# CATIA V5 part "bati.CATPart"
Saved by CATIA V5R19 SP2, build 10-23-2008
Part number: bati
Material "Acier": density 7860 kg/m3, Young's modulus 2e+11 Pa, Poisson ratio 0.266, thermal expansion 1.17e-05 1/K
Material "Bleu clair DS": density 7860 kg/m3, Young's modulus 2e+11 Pa, Poisson ratio 0.266
Bounding box of the stored display mesh (mm): x -60 to 60, y -200 to 200, z 0 to 190
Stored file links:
  C:\Documents and Settings\jboiteux\Bureau\iao_jboiteux\Catia\non optiisé\iao final\bati.CATPart
  C:\iao\acanisme a coulisseau.CATProduct
  C:\iao\squelette bati.CATPart
  C:\Appli\Dassault Systemes\B20\intel_a\startup\materials\French\Catalog.CATMaterial
  C:\Appli\Dassault Systemes\B20\intel_a\startup\materials\bright_oak.jpg
  C:\Appli\Dassault Systemes\B20\intel_a\startup\materials\blue_env_512x512.jpg
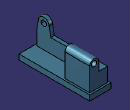
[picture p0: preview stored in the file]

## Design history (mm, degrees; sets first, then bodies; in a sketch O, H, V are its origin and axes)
Parameters
  taille = 10 mm
Set1
  Plane1 to Plane3: linked copy from another document
Body1 (main body), material "Acier"
  Sketch1 on xy-plane, origin (0, 0, 0), H (1, 0, 0), V (0, 1, 0)
    line L1 (-60, 200) -> (60, 200)
    line L2 (60, 200) -> (60, -200)
    line L3 (60, -200) -> (-60, -200)
    line L4 (-60, -200) -> (-60, 200)
    distance H L3 = 200 {= taille *20}
    distance L1 H = 200 {= taille *20}
    distance V L2 = 60 {= taille *6}
    distance L4 V = 60 {= taille *6}
    horizontal: L1 H, L3 H
    vertical: L2 V, L4 V
  Pad1: profile Sketch1, direction (0, 0, 1), length 30 {= taille *3}
  Sketch2 on end face of Pad1, origin (0, 0, 30), H (1, 0, 0), V (0, 1, 0)
    point P1 (0, 190)
    line L1 (0, 190) -> (50, 190)
    line L2 (50, 190) -> (50, 50)
    line L3 (50, 50) -> (0, 50)
    line L4 (0, 50) -> (0, 190)
    reference projected line E1 (60, -20) -> (60, 20) from edge [face of Pad1 from Sketch1.L2 | end face of Pad1]
    reference projected line E2 (6, 200) -> (-6, 200) from edge [face of Pad1 from Sketch1.L1 | end face of Pad1]
    distance L2 E1 = 10 {= taille}
    distance E2 L1 = 10 {= taille}
    length L2 = 140 {= taille*14}
    angle L4 L3 = 90
    coincidence: P1 V
    horizontal: L1 H
    vertical: L4 V
  Pad2: profile Sketch2, direction (0, 0, 1), length 130 {= taille *13}
  Sketch3 on face of Pad2 from Sketch2.L3, origin (0, 50, 0), H (1, 0, 0), V (0, 0, 1)
    arc A1 centre (25, 160) radius 25 from (50, 160) to (0, 160) ccw
    point P1 (25, 160)
    point P2 (0, 160)
    point P3 (50, 160)
    line L1 (0, 160) -> (50, 160)
    reference projected line E1 (0, 160) -> (6, 160) from edge [face of Pad2 from Sketch2.L3 | end face of Pad2]
    reference projected line E2 (0, 3) -> (0, 16) from edge [face of Pad2 from Sketch2.L3 | face of Pad2 from Sketch2.L4]
    reference projected line E3 (50, 3) -> (50, 16) from edge [face of Pad2 | face of Pad2 from Sketch2.L3]
    coincidence: P2 V, L1 P1, E1 L1, E2 P2, E3 P3
  Pad3: profile Sketch3, direction (0, 1, 0), length 140 {= taille *14}
  Sketch4 on face of Pad1 from Sketch1.L3, origin (0, -200, 0), H (1, 0, 0), V (0, 0, 1)
    line L1 (-50, 30) -> (-30, 30)
    line L2 (-30, 30) -> (-30, 110)
    line L3 (-30, 110) -> (-50, 110)
    line L4 (-50, 110) -> (-50, 30)
    reference projected line E1 (-6, 30) -> (6, 30) from edge [face of Pad1 from Sketch1.L3 | end face of Pad1]
    reference projected line E2 (-60, 0) -> (-60, 3) from edge [face of Pad1 from Sketch1.L3 | face of Pad1 from Sketch1.L4]
    length L2 = 80 {= taille *8}
    length L3 = 20 {= taille *2}
    distance E2 L4 = 10 {= taille}
    horizontal: L1 H, L3 H
    vertical: L2 V, L4 V
    coincidence: E1 L1
  Pad4: profile Sketch4, direction (0, 1, 0), length 390 {= taille*39}, opposite side length -10 {= -taille}
  Sketch5 on face of Pad2 from Sketch2.L4, origin (0, 0, 0), H (0, -1, 0), V (0, 0, 1)
    line L1 (-190, 110) -> (-50, 110)
    line L2 (-50, 110) -> (-50, 30)
    line L3 (-50, 30) -> (-190, 30)
    line L4 (-190, 30) -> (-190, 110)
    reference projected line E1 (19, 110) -> (-19, 110) from edge [face of Pad4 from Sketch4.L3 | face of Pad4 from Sketch4.L4]
    reference projected line E2 (-20, 30) -> (20, 30) from edge [face of Pad1 from Sketch1.L4 | end face of Pad1]
    reference projected line E3 (-190, 11) -> (-190, 3) from edge [face of Pad4 | face of Pad4]
    reference projected line E4 (-50, 3) -> (-50, 16) from edge [face of Pad2 from Sketch2.L2 | face of Pad3]
    horizontal: L1 H, L3 H
    vertical: L2 V, L4 V
    coincidence: E1 L1, E2 L3, E3 L4, E4 L2
  Pad5: profile Sketch5, direction (-1, 0, 0), up to the existing solid (limit type 2)
  Sketch6 on face of Pad4 from Sketch4.L2, origin (-30, 0, 0), H (0, 1, 0), V (0, 0, 1)
    arc A1 centre (-150, 160) radius 30 from (-120, 160) to (-180, 160) ccw
    point P1 (-150, 160)
    point P2 (-120, 160)
    point P3 (-180, 160)
    line L1 (-120, 160) -> (-110, 110)
    point P4 (-110, 110)
    point P5 (-110, 110)
    line L2 (-110, 110) -> (-190, 110)
    point P6 (-190, 110)
    line L3 (-190, 110) -> (-180, 160)
    reference projected line E1 (-19, 110) -> (19, 110) from edge [face of Pad4 from Sketch4.L2 | face of Pad4]
    reference projected point E2 (-190, 110) from vertex [start face of Pad4 | face of Pad4 from Sketch4.L3 | face of Pad4 from Sketch4.L2]
    reference projected line E3 (-200, 0) -> (-200, 3) from edge [face of Pad1 from Sketch1.L2 | face of Pad1 from Sketch1.L3]
    distance P6 P5 = 80 {= taille *8}
    distance P2 P3 = 60 {= taille *6}
    distance P3 P1 = 30 {= taille*3}
    distance P1 L2 = 50 {= taille *5}
    distance P2 L2 = 50 {= taille *5}
    distance P1 E3 = 50 {= taille*5}
    horizontal: L2 H
    coincidence: P5 P4, E1 L2, E2 P6
  Pad6: profile Sketch6, direction (-1, 0, 0), up to face of Pad4 from Sketch4.L4
  Sketch7 on face of Pad4, origin (-50, -15.2449, 16.9389), H (0, 1, 0), V (0, 0, -1)
    point P1 (-134.7551, -143.0611)
    reference projected arc E1 centre (-134.7551, -143.0611) radius 30 from (-164.7551, -143.0611) to (-104.7551, -143.0611) ccw from edge [end face of Pad6 | face of Pad6 from Sketch6.A1]
    concentricity: E1 P1
  Hole1: placed by Sketch7, at (-50, -150, 160) direction (1, 0, 0), diameter 30 {= taille*3}, through (limit type 6)
  Sketch8 on face of Pad3, origin (2.1484, 50, 16), H (1, 0, 0), V (0, 0, 1)
    point P1 (22.8516, 144)
    reference projected arc E1 centre (22.8516, 144) radius 25 from (47.8516, 144) to (-2.1484, 144) ccw from edge [face of Pad3 from Sketch3.A1 | face of Pad3]
    concentricity: E1 P1
  Hole2: placed by Sketch8, at (25, 50, 160) direction (0, 1, 0), diameter 30 {= taille*3}, through (limit type 6)
Relations
  Sketch2.length(L2) = bati\taille *14 (deactivated)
